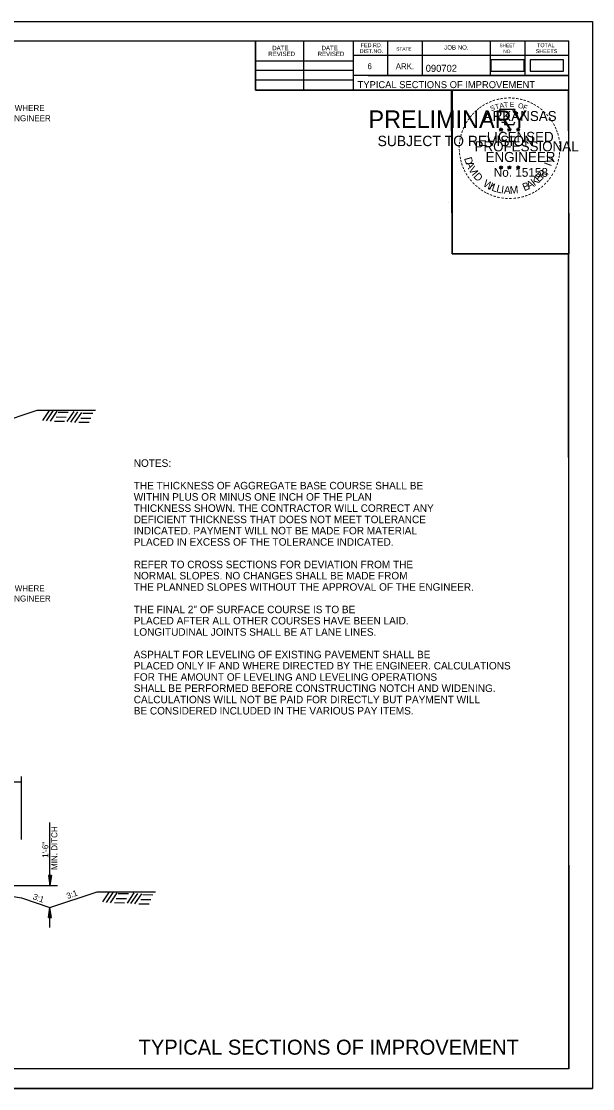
# Model space of a CAD drawing. Extents: x 1371763 to 1372860, y 385599 to 385872.
# Drawn here: x 1372402.6 to 1372459.7, y 385598.6 to 385705.3 of the extents above; entities that cross this region are included whole.
import ezdxf

# ---------------------------------------------------------------- set-up
doc = ezdxf.new("R2010")
doc.units = 0
for name, color, linetype in [('R_Border', 7, 'Continuous'), ('R_Border PE', 7, 'Continuous'), ('R_Border Prem', 7, 'Continuous'), ('R_Dimension', 7, 'Continuous'), ('R_Draft', 7, 'Continuous'), ('R_Fin Surface', 7, 'Continuous'), ('R_No Plot', 7, 'Continuous')]:
    doc.layers.add(name, color=color, linetype=linetype)

msp = doc.modelspace()

# ---------------------------------------------------------------- linework, layer by layer
at = {"layer": 'R_Border'}
for p, q in [((1372299.21, 385703.31), (1372457.3, 385703.31)), ((1372425.98, 385698.37), (1372425.98, 385703.31)), ((1372430.82, 385698.37), (1372430.82, 385703.31)), ((1372435.75, 385703.31), (1372435.75, 385698.37)), ((1372439.17, 385703.31), (1372439.17, 385699.84)), ((1372442.64, 385703.31), (1372442.64, 385699.84)), ((1372449.43, 385703.31), (1372449.43, 385699.84)), ((1372452.9, 385703.31), (1372452.9, 385699.84)), ((1372457.3, 385600.58), (1372457.3, 385703.31)), ((1372457.3, 385701.84), (1372435.75, 385701.84)), ((1372457.3, 385701.85), (1372457.3, 385701.85)), ((1372425.98, 385701.3), (1372435.75, 385701.3)), ((1372425.98, 385700.37), (1372435.75, 385700.37)), ((1372457.3, 385699.84), (1372435.75, 385699.84)), ((1372437.23, 385699.84), (1372457.3, 385699.84)), ((1372425.98, 385699.4), (1372435.75, 385699.4)), ((1372457.3, 385698.37), (1372425.98, 385698.37)), ((1372457.3, 385600.58), (1372299.21, 385600.58))]:
    msp.add_line(p, q, dxfattribs=at)
at = {"layer": 'R_Border PE'}
for p, q in [((1372450.34, 385694.49), (1372450.51, 385694.44)), ((1372450.34, 385694.49), (1372450.47, 385694.47)), ((1372450.34, 385694.49), (1372450.46, 385694.43)), ((1372450.41, 385694.29), (1372450.51, 385694.44)), ((1372450.41, 385694.29), (1372450.47, 385694.41)), ((1372450.41, 385694.29), (1372450.51, 385694.4)), ((1372450.51, 385694.62), (1372450.49, 385694.5)), ((1372450.51, 385694.44), (1372450.51, 385694.62)), ((1372450.51, 385694.62), (1372450.54, 385694.5)), ((1372450.69, 385694.49), (1372450.51, 385694.44)), ((1372450.62, 385694.29), (1372450.51, 385694.44)), ((1372450.62, 385694.29), (1372450.51, 385694.4)), ((1372450.69, 385694.49), (1372450.55, 385694.47)), ((1372450.62, 385694.29), (1372450.55, 385694.44)), ((1372450.69, 385694.49), (1372450.59, 385694.44)), ((1372451.18, 385694.49), (1372451.35, 385694.44)), ((1372451.18, 385694.49), (1372451.3, 385694.47)), ((1372451.18, 385694.49), (1372451.29, 385694.43)), ((1372451.24, 385694.29), (1372451.35, 385694.44)), ((1372451.24, 385694.29), (1372451.3, 385694.41)), ((1372451.24, 385694.29), (1372451.35, 385694.4)), ((1372451.35, 385694.62), (1372451.33, 385694.5)), ((1372451.35, 385694.44), (1372451.35, 385694.62)), ((1372451.35, 385694.62), (1372451.37, 385694.5)), ((1372451.52, 385694.49), (1372451.35, 385694.44)), ((1372451.46, 385694.29), (1372451.35, 385694.44)), ((1372451.46, 385694.29), (1372451.35, 385694.4)), ((1372451.52, 385694.49), (1372451.38, 385694.47)), ((1372451.46, 385694.29), (1372451.39, 385694.44)), ((1372451.52, 385694.49), (1372451.42, 385694.44)), ((1372452.06, 385694.49), (1372452.23, 385694.43)), ((1372452.06, 385694.49), (1372452.18, 385694.47)), ((1372452.06, 385694.49), (1372452.18, 385694.43)), ((1372452.12, 385694.28), (1372452.23, 385694.43)), ((1372452.12, 385694.28), (1372452.19, 385694.41)), ((1372452.12, 385694.28), (1372452.23, 385694.39)), ((1372452.23, 385694.62), (1372452.21, 385694.49)), ((1372452.23, 385694.43), (1372452.23, 385694.62)), ((1372452.23, 385694.62), (1372452.26, 385694.49)), ((1372452.41, 385694.49), (1372452.23, 385694.43)), ((1372452.34, 385694.28), (1372452.23, 385694.43)), ((1372452.34, 385694.28), (1372452.23, 385694.39)), ((1372452.41, 385694.49), (1372452.26, 385694.46)), ((1372452.34, 385694.28), (1372452.27, 385694.43)), ((1372452.41, 385694.49), (1372452.3, 385694.44)), ((1372450.34, 385690.71), (1372450.51, 385690.65)), ((1372450.34, 385690.71), (1372450.46, 385690.69)), ((1372450.34, 385690.71), (1372450.46, 385690.65)), ((1372450.4, 385690.5), (1372450.51, 385690.65)), ((1372450.4, 385690.5), (1372450.47, 385690.63)), ((1372450.4, 385690.5), (1372450.51, 385690.61)), ((1372450.51, 385690.83), (1372450.49, 385690.71)), ((1372450.51, 385690.65), (1372450.51, 385690.83)), ((1372450.51, 385690.83), (1372450.54, 385690.71)), ((1372450.69, 385690.71), (1372450.51, 385690.65)), ((1372450.62, 385690.5), (1372450.51, 385690.65)), ((1372450.62, 385690.5), (1372450.51, 385690.61)), ((1372450.69, 385690.71), (1372450.54, 385690.68)), ((1372450.62, 385690.5), (1372450.55, 385690.65)), ((1372450.69, 385690.71), (1372450.58, 385690.66)), ((1372451.17, 385690.71), (1372451.35, 385690.65)), ((1372451.17, 385690.71), (1372451.3, 385690.69)), ((1372451.17, 385690.71), (1372451.29, 385690.65)), ((1372451.24, 385690.5), (1372451.35, 385690.65)), ((1372451.24, 385690.5), (1372451.3, 385690.63)), ((1372451.24, 385690.5), (1372451.35, 385690.61)), ((1372451.35, 385690.83), (1372451.33, 385690.71)), ((1372451.35, 385690.65), (1372451.35, 385690.83)), ((1372451.35, 385690.83), (1372451.37, 385690.71)), ((1372451.52, 385690.71), (1372451.35, 385690.65)), ((1372451.45, 385690.5), (1372451.35, 385690.65)), ((1372451.45, 385690.5), (1372451.35, 385690.61)), ((1372451.52, 385690.71), (1372451.38, 385690.68)), ((1372451.45, 385690.5), (1372451.39, 385690.65)), ((1372451.52, 385690.71), (1372451.42, 385690.66)), ((1372452.06, 385690.7), (1372452.23, 385690.65)), ((1372452.06, 385690.7), (1372452.18, 385690.68)), ((1372452.06, 385690.7), (1372452.17, 385690.64)), ((1372452.12, 385690.5), (1372452.23, 385690.65)), ((1372452.12, 385690.5), (1372452.19, 385690.62)), ((1372452.12, 385690.5), (1372452.23, 385690.61)), ((1372452.23, 385690.83), (1372452.21, 385690.7)), ((1372452.23, 385690.65), (1372452.23, 385690.83)), ((1372452.23, 385690.83), (1372452.26, 385690.7)), ((1372452.4, 385690.7), (1372452.23, 385690.65)), ((1372452.34, 385690.5), (1372452.23, 385690.65)), ((1372452.34, 385690.5), (1372452.23, 385690.61)), ((1372452.4, 385690.7), (1372452.26, 385690.68)), ((1372452.34, 385690.5), (1372452.27, 385690.64)), ((1372452.4, 385690.7), (1372452.3, 385690.65))]:
    msp.add_line(p, q, dxfattribs=at)
for points in [[(1372450.36, 385696.43), (1372450.5, 385696.02)], [(1372452.12, 385695.97), (1372452.19, 385696.11), (1372451.84, 385696.1), (1372451.92, 385696.43), (1372450.36, 385696.43)], [(1372450.61, 385695.22), (1372450.61, 385695.18), (1372450.89, 385695.17), (1372450.86, 385694.93), (1372451.8, 385694.93), (1372451.9, 385695.2)], [(1372450.51, 385694.62), (1372450.62, 385694.29), (1372450.34, 385694.49), (1372450.69, 385694.49), (1372450.41, 385694.29), (1372450.51, 385694.62)], [(1372451.35, 385694.62), (1372451.46, 385694.29), (1372451.18, 385694.49), (1372451.52, 385694.49), (1372451.24, 385694.29), (1372451.35, 385694.62)], [(1372452.23, 385694.62), (1372452.34, 385694.28), (1372452.06, 385694.49), (1372452.41, 385694.49), (1372452.12, 385694.28), (1372452.23, 385694.62)], [(1372450.51, 385690.83), (1372450.62, 385690.5), (1372450.34, 385690.71), (1372450.69, 385690.71), (1372450.4, 385690.5), (1372450.51, 385690.83)], [(1372451.35, 385690.83), (1372451.45, 385690.5), (1372451.17, 385690.71), (1372451.52, 385690.71), (1372451.24, 385690.5), (1372451.35, 385690.83)], [(1372452.23, 385690.83), (1372452.34, 385690.5), (1372452.06, 385690.7), (1372452.4, 385690.7), (1372452.12, 385690.5), (1372452.23, 385690.83)]]:
    msp.add_lwpolyline(points, dxfattribs=at)
for centre, radius in [((1372450.51, 385694.44), 0.0861), ((1372450.51, 385694.44), 0.0723), ((1372450.51, 385694.44), 0.0579), ((1372450.51, 385694.44), 0.0495), ((1372450.51, 385694.44), 0.0374), ((1372450.51, 385694.44), 0.0248), ((1372450.51, 385694.44), 0.0148), ((1372451.35, 385694.44), 0.0861), ((1372451.35, 385694.44), 0.0723), ((1372451.35, 385694.44), 0.0579), ((1372451.35, 385694.44), 0.0495), ((1372451.35, 385694.44), 0.0374), ((1372451.35, 385694.44), 0.0248), ((1372451.35, 385694.44), 0.0148), ((1372452.23, 385694.43), 0.0861), ((1372452.23, 385694.43), 0.0723), ((1372452.23, 385694.43), 0.0579), ((1372452.23, 385694.43), 0.0495), ((1372452.23, 385694.43), 0.0374), ((1372452.23, 385694.43), 0.0248), ((1372452.23, 385694.43), 0.0148), ((1372450.51, 385690.65), 0.0861), ((1372450.51, 385690.65), 0.0723), ((1372450.51, 385690.65), 0.0579), ((1372450.51, 385690.65), 0.0495), ((1372450.51, 385690.65), 0.0374), ((1372450.51, 385690.65), 0.0248), ((1372450.51, 385690.65), 0.0148), ((1372451.35, 385690.65), 0.0861), ((1372451.35, 385690.65), 0.0723), ((1372451.35, 385690.65), 0.0579), ((1372451.35, 385690.65), 0.0495), ((1372451.35, 385690.65), 0.0374), ((1372451.35, 385690.65), 0.0248), ((1372451.35, 385690.65), 0.0148), ((1372452.23, 385690.65), 0.0861), ((1372452.23, 385690.65), 0.0723), ((1372452.23, 385690.65), 0.0579), ((1372452.23, 385690.65), 0.0495), ((1372452.23, 385690.65), 0.0374), ((1372452.23, 385690.65), 0.0248), ((1372452.23, 385690.65), 0.0148)]:
    msp.add_circle(centre, radius, dxfattribs=at)
at = {"layer": 'R_Draft'}
for p, q in [((1372404.72, 385665.36), (1372405.4, 385666.37)), ((1372405.08, 385665.32), (1372405.75, 385666.32)), ((1372405.48, 385665.28), (1372406.15, 385666.28)), ((1372406.05, 385665.72), (1372407.07, 385665.71)), ((1372406.25, 385666.21), (1372407.27, 385666.2)), ((1372407.17, 385665.26), (1372407.85, 385666.26)), ((1372407.53, 385665.21), (1372408.21, 385666.22)), ((1372407.93, 385665.17), (1372408.61, 385666.17)), ((1372408.51, 385665.61), (1372409.53, 385665.61)), ((1372408.71, 385666.1), (1372409.73, 385666.09)), ((1372405.88, 385665.3), (1372406.9, 385665.29)), ((1372408.33, 385665.19), (1372409.35, 385665.18)), ((1372378.58, 385629.25), (1372402.58, 385629.25)), ((1372402.58, 385623.49), (1372402.58, 385629.79)), ((1372405.43, 385618.88), (1372405.43, 385625.18)), ((1372386.58, 385620.31), (1372402.58, 385617.64)), ((1372405.28, 385619.88), (1372405.43, 385618.88)), ((1372405.58, 385619.88), (1372405.28, 385619.88)), ((1372405.3, 385619.88), (1372405.43, 385619.05)), ((1372405.33, 385619.88), (1372405.43, 385619.22)), ((1372405.35, 385619.88), (1372405.43, 385619.39)), ((1372405.38, 385619.88), (1372405.43, 385619.56)), ((1372405.4, 385619.88), (1372405.43, 385619.72)), ((1372405.58, 385619.88), (1372405.43, 385618.88)), ((1372405.47, 385619.88), (1372405.43, 385619.56)), ((1372405.52, 385619.88), (1372405.43, 385619.22)), ((1372405.55, 385619.88), (1372405.43, 385619.05)), ((1372405.5, 385619.88), (1372405.43, 385619.39)), ((1372405.45, 385619.88), (1372405.43, 385619.72)), ((1372397.32, 385618.88), (1372406.18, 385618.88)), ((1372410.72, 385617.24), (1372411.4, 385618.25)), ((1372411.08, 385617.2), (1372411.76, 385618.2)), ((1372411.48, 385617.16), (1372412.16, 385618.16)), ((1372412.06, 385617.6), (1372413.07, 385617.59)), ((1372412.26, 385618.09), (1372413.28, 385618.08)), ((1372413.17, 385617.13), (1372413.85, 385618.14)), ((1372413.53, 385617.09), (1372414.21, 385618.09)), ((1372413.93, 385617.05), (1372414.61, 385618.05)), ((1372414.51, 385617.49), (1372415.53, 385617.49)), ((1372414.71, 385617.98), (1372415.73, 385617.97)), ((1372405.28, 385615.69), (1372405.43, 385616.69)), ((1372405.3, 385615.69), (1372405.43, 385616.53)), ((1372405.33, 385615.69), (1372405.43, 385616.35)), ((1372405.58, 385615.69), (1372405.43, 385616.69)), ((1372405.43, 385614.69), (1372405.43, 385616.69)), ((1372405.55, 385615.69), (1372405.43, 385616.53)), ((1372405.52, 385615.69), (1372405.43, 385616.35)), ((1372411.88, 385617.18), (1372412.9, 385617.17)), ((1372414.33, 385617.07), (1372415.35, 385617.06)), ((1372405.28, 385615.69), (1372405.58, 385615.69)), ((1372405.35, 385615.69), (1372405.43, 385616.19)), ((1372405.38, 385615.69), (1372405.43, 385616.02)), ((1372405.4, 385615.69), (1372405.43, 385615.85)), ((1372405.5, 385615.69), (1372405.43, 385616.19)), ((1372405.47, 385615.69), (1372405.43, 385616.02)), ((1372405.45, 385615.69), (1372405.43, 385615.85))]:
    msp.add_line(p, q, dxfattribs=at)
for points in [[(1372449.49, 385700.26), (1372452.83, 385700.26), (1372452.83, 385701.41), (1372449.49, 385701.41)], [(1372453.43, 385700.26), (1372456.77, 385700.26), (1372456.77, 385701.41), (1372453.43, 385701.41)]]:
    msp.add_lwpolyline(points, close=True, dxfattribs=at)
at = {"layer": 'R_Fin Surface'}
for p, q in [((1372399.42, 385664.81), (1372404.17, 385666.4)), ((1372404.17, 385666.4), (1372409.98, 385666.4)), ((1372402.58, 385617.64), (1372405.43, 385616.69)), ((1372405.43, 385616.69), (1372410.17, 385618.27)), ((1372410.17, 385618.27), (1372415.99, 385618.27))]:
    msp.add_line(p, q, dxfattribs=at)
at = {"layer": 'R_No Plot'}
for p, q in [((1372293.01, 385705.25), (1372459.67, 385705.25)), ((1372445.31, 385687.14), (1372445.31, 385687.14)), ((1372293.01, 385598.59), (1372459.67, 385598.59))]:
    msp.add_line(p, q, dxfattribs=at)
for points in [[(1372293, 385705.25), (1372459.67, 385705.25), (1372459.67, 385598.59), (1372293, 385598.59)], [(1372416.17, 385703.31), (1372425.98, 385703.31), (1372425.98, 385698.37), (1372434.03, 385698.37), (1372445.63, 385698.37), (1372445.63, 385682.03), (1372457.24, 385682.03), (1372457.3, 385600.58), (1372299.21, 385600.58), (1372299.21, 385703.31)], [(1372445.56, 385698.37), (1372457.24, 385698.37), (1372457.31, 385682.03), (1372445.63, 385682.03)]]:
    msp.add_lwpolyline(points, close=True, dxfattribs=at)

# ---------------------------------------------------------------- texts
at = {"layer": 'R_Border'}
for s, height, p in [('DATE', 0.44, (1372427.65, 385702.37)), ('DATE', 0.44, (1372432.58, 385702.37)), ('FED.RD.', 0.391, (1372436.49, 385702.67)), ('STATE', 0.342, (1372440.05, 385702.33)), ('JOB NO.', 0.44, (1372444.84, 385702.43)), ('SHEET', 0.342, (1372450.36, 385702.67)), ('TOTAL', 0.391, (1372454.12, 385702.67)), ('REVISED', 0.44, (1372427.26, 385701.78)), ('REVISED', 0.44, (1372432.19, 385701.78)), ('DIST.NO.', 0.391, (1372436.39, 385702.08)), ('NO.', 0.342, (1372450.75, 385702.08)), ('SHEETS', 0.391, (1372453.98, 385702.08)), ('6', 0.586, (1372437.17, 385700.47)), ('ARK.', 0.586, (1372440, 385700.47)), ('090702', 0.7, (1372442.99, 385700.21)), ('TYPICAL SECTIONS OF IMPROVEMENT', 0.7, (1372436.18, 385698.58))]:
    msp.add_text(s, height=height, dxfattribs=at).set_placement(p)
at = {"layer": 'R_Border PE'}
for s, height, rotation, p in [('-', 0.8, 19.1761, (1372449.73, 385697)), ('-', 0.8, 13.6302, (1372450.11, 385697.12)), ('-', 0.8, 10.2193, (1372450.45, 385697.2)), ('-', 0.8, 5.8968, (1372450.81, 385697.25)), ('-', 0.8, 0.1862, (1372451.2, 385697.29)), ('-', 0.8, 357.743, (1372451.56, 385697.28)), ('-', 0.8, 352.1617, (1372451.93, 385697.25)), ('-', 0.8, 347.2049, (1372452.29, 385697.2)), ('-', 0.8, 342.3362, (1372452.61, 385697.12)), ('-', 0.8, 337.8551, (1372452.98, 385697.01)), ('-', 0.8, 42.9622, (1372448.06, 385695.92)), ('-', 0.8, 38.9507, (1372448.28, 385696.13)), ('-', 0.8, 36.2317, (1372448.51, 385696.32)), ('-', 0.8, 34.0636, (1372448.8, 385696.52)), ('-', 0.8, 28.7918, (1372449.1, 385696.7)), ('-', 0.8, 24.3072, (1372449.42, 385696.86)), ('S', 0.5, 21.594, (1372449.54, 385696.27)), ('T', 0.5, 16.4036, (1372450, 385696.44)), ('A', 0.5, 11.2132, (1372450.41, 385696.56)), ('T', 0.5, 6.0228, (1372450.83, 385696.65)), ('E', 0.5, 0.8323, (1372451.39, 385696.7)), ('O', 0.5, 350.4515, (1372452.19, 385696.6)), ('F', 0.5, 340.0707, (1372452.66, 385696.48)), ('-', 0.8, 334.1211, (1372453.29, 385696.87)), ('-', 0.8, 329.6409, (1372453.58, 385696.73)), ('-', 0.8, 325.8627, (1372453.9, 385696.55)), ('-', 0.8, 320.5297, (1372454.21, 385696.34)), ('-', 0.8, 315.5786, (1372454.51, 385696.09)), ('-', 0.8, 58.0706, (1372447.26, 385694.89)), ('-', 0.8, 54.2325, (1372447.43, 385695.16)), ('-', 0.8, 50.6142, (1372447.63, 385695.44)), ('-', 0.8, 48.4231, (1372447.84, 385695.68)), ('-', 0.8, 309.8797, (1372454.79, 385695.82)), ('-', 0.8, 306.6522, (1372455.06, 385695.52)), ('-', 0.7, 303.6753, (1372455.3, 385695.23)), ('-', 0.8, 72.3945, (1372446.87, 385693.97)), ('-', 0.8, 67.7743, (1372446.98, 385694.28)), ('-', 0.8, 62.8713, (1372447.11, 385694.59)), ('-', 0.8, 299.6684, (1372455.46, 385694.93)), ('-', 0.8, 294.6628, (1372455.62, 385694.62)), ('-', 0.8, 290.5728, (1372455.75, 385694.34)), ('-', 0.8, 85.1863, (1372446.67, 385692.91)), ('-', 0.8, 81.2013, (1372446.7, 385693.25)), ('-', 0.8, 75.461, (1372446.77, 385693.61)), ('-', 0.8, 285.1233, (1372455.87, 385694.05)), ('-', 0.8, 280.5493, (1372455.97, 385693.68)), ('-', 0.8, 276.5962, (1372456.05, 385693.29)), ('-', 0.8, 89.0622, (1372446.65, 385692.56)), ('-', 0.8, 94.1959, (1372446.67, 385692.2)), ('-', 0.8, 98.9479, (1372446.71, 385691.86)), ('-', 0.8, 263.5172, (1372456.08, 385692.28)), ('-', 0.8, 274.3301, (1372456.08, 385692.93)), ('-', 0.8, 269.9407, (1372456.09, 385692.61)), ('-', 0.8, 101.7149, (1372446.78, 385691.5)), ('-', 0.8, 105.4578, (1372446.86, 385691.2)), ('-', 0.8, 109.0874, (1372446.96, 385690.88)), ('D', 0.77, 286.2848, (1372446.82, 385691.56)), ('A', 0.77, 292.7835, (1372446.97, 385691.06)), ('I', 0.77, 69.0301, (1372455.5, 385690.71)), ('V', 0.77, 72.6573, (1372455.62, 385690.98)), ('-', 0.8, 252.8681, (1372455.9, 385691.26)), ('-', 0.8, 255.7626, (1372455.99, 385691.62)), ('-', 0.8, 260.9953, (1372456.05, 385691.95)), ('-', 0.8, 114.0643, (1372447.09, 385690.58)), ('-', 0.8, 115.7289, (1372447.24, 385690.28)), ('-', 0.8, 120.4471, (1372447.42, 385689.98)), ('V', 0.77, 300.7936, (1372447.22, 385690.47)), ('I', 0.77, 308.3502, (1372447.54, 385689.96)), ('D', 0.77, 311.9774, (1372447.71, 385689.72)), ('E', 0.77, 44.0175, (1372454.31, 385689.12)), ('R', 0.77, 50.3651, (1372454.68, 385689.47)), (',', 0.77, 57.4684, (1372455.04, 385689.91)), ('-', 0.8, 239.0712, (1372455.46, 385690.23)), ('-', 0.8, 244.6197, (1372455.66, 385690.6)), ('-', 0.8, 247.8887, (1372455.79, 385690.92)), ('-', 0.8, 125.8934, (1372447.62, 385689.7)), ('-', 0.8, 130.7181, (1372447.85, 385689.43)), ('-', 0.8, 134.2238, (1372448.11, 385689.15)), ('-', 0.8, 138.9338, (1372448.38, 385688.92)), ('W', 0.77, 328.0731, (1372448.65, 385688.84)), ('I', 0.77, 336.6877, (1372449.25, 385688.48)), ('L', 0.77, 340.3149, (1372449.51, 385688.36)), ('L', 0.77, 346.6625, (1372449.99, 385688.19)), ('I', 0.77, 353.0101, (1372450.49, 385688.07)), ('A', 0.77, 356.6373, (1372450.78, 385688.03)), ('M', 0.77, 4.6473, (1372451.42, 385688)), ('B', 0.77, 22.8589, (1372452.85, 385688.27)), ('A', 0.77, 28.9042, (1372453.3, 385688.45)), ('K', 0.77, 36.9143, (1372453.86, 385688.77)), ('-', 0.8, 221.0851, (1372454.55, 385689.08)), ('-', 0.8, 225.7653, (1372454.81, 385689.34)), ('-', 0.8, 231.2538, (1372455.05, 385689.62)), ('-', 0.8, 233.8452, (1372455.26, 385689.9)), ('-', 0.8, 144.6463, (1372448.65, 385688.72)), ('-', 0.8, 148.0898, (1372448.93, 385688.53)), ('-', 0.8, 151.5704, (1372449.22, 385688.37)), ('-', 0.8, 154.6002, (1372449.48, 385688.25)), ('-', 0.8, 158.5612, (1372449.8, 385688.12)), ('-', 0.8, 162.7983, (1372450.14, 385688.01)), ('-', 0.8, 167.5555, (1372450.5, 385687.93)), ('-', 0.8, 195.4743, (1372452.77, 385688.06)), ('-', 0.8, 199.4643, (1372453.1, 385688.18)), ('-', 0.8, 204.2516, (1372453.41, 385688.32)), ('-', 0.8, 207.3568, (1372453.73, 385688.48)), ('-', 0.8, 212.2491, (1372454.01, 385688.65)), ('-', 0.8, 215.7363, (1372454.27, 385688.85)), ('-', 0.8, 173.1155, (1372450.88, 385687.88)), ('-', 0.8, 176.5183, (1372451.26, 385687.85)), ('-', 0.8, 181.5918, (1372451.63, 385687.86)), ('-', 0.8, 185.8167, (1372452.03, 385687.9)), ('-', 0.8, 191.2858, (1372452.4, 385687.96))]:
    msp.add_text(s, height=height, rotation=rotation, dxfattribs=at).set_placement(p)
for s, height, p in [('ARKANSAS', 1, (1372448.79, 385695.29)), ('LICENSED', 1, (1372449.09, 385693.21)), ('PROFESSIONAL', 1, (1372447.87, 385692.26)), ('ENGINEER', 1, (1372448.97, 385691.2)), ('No. 15158', 0.878, (1372449.79, 385689.72)), ('AAMU', 0.00001, (1372451.31, 385688))]:
    msp.add_text(s, height=height, dxfattribs=at).set_placement(p)
at = {"layer": 'R_Border Prem'}
for s, height, p in [('PRELIMINARY', 1.75, (1372437.27, 385694.6)), ('DWB', 0.005, (1372437.65, 385695.52)), ('SUBJECT TO REVISION', 1.0376, (1372438.18, 385692.78))]:
    msp.add_text(s, height=height, dxfattribs=at).set_placement(p)
at = {"layer": 'R_Dimension'}
msp.add_text('TYPICAL SECTIONS OF IMPROVEMENT', height=1.5, dxfattribs=at).set_placement((1372414.3, 385601.98))
at = {"layer": 'R_Draft'}
for s, rotation, p in [('*TO BE USED IF AND WHERE ', 360, (1372393.67, 385696.29)), ('DIRECTED BY THE ENGINEER', 360, (1372393.88, 385695.27)), ('*TO BE USED IF AND WHERE ', 360, (1372393.67, 385648.29)), ('DIRECTED BY THE ENGINEER', 360, (1372393.88, 385647.27)), ('MIN. DITCH', 90, (1372406.17, 385620.44)), ('1\'-6"', 90, (1372405.27, 385621.65)), ('3:1', 19.9978, (1372407.21, 385617.53)), ('3:1', 340.0022, (1372403.67, 385617.54))]:
    msp.add_text(s, height=0.6, rotation=rotation, dxfattribs=at).set_placement(p)
for s, p in [('NOTES:', (1372413.81, 385660.73)), ('THE THICKNESS OF AGGREGATE BASE COURSE SHALL BE', (1372413.81, 385658.48)), ('WITHIN PLUS OR MINUS ONE INCH OF THE PLAN', (1372413.81, 385657.35)), ('THICKNESS SHOWN. THE CONTRACTOR WILL CORRECT ANY', (1372413.81, 385656.23)), ('DEFICIENT THICKNESS THAT DOES NOT MEET TOLERANCE ', (1372413.81, 385655.1)), ('INDICATED. PAYMENT WILL NOT BE MADE FOR MATERIAL', (1372413.81, 385653.98)), ('PLACED IN EXCESS OF THE TOLERANCE INDICATED.', (1372413.81, 385652.85)), ('REFER TO CROSS SECTIONS FOR DEVIATION FROM THE', (1372413.81, 385650.6)), ('NORMAL SLOPES. NO CHANGES SHALL BE MADE FROM', (1372413.81, 385649.48)), ('THE PLANNED SLOPES WITHOUT THE APPROVAL OF THE ENGINEER.', (1372413.81, 385648.35)), ('THE FINAL 2" OF SURFACE COURSE IS TO BE', (1372413.81, 385646.1)), ('PLACED AFTER ALL OTHER COURSES HAVE BEEN LAID.', (1372413.81, 385644.98)), ('LONGITUDINAL JOINTS SHALL BE AT LANE LINES.', (1372413.81, 385643.85)), ('ASPHALT FOR LEVELING OF EXISTING PAVEMENT SHALL BE', (1372413.81, 385641.6)), ('PLACED ONLY IF AND WHERE DIRECTED BY THE ENGINEER. CALCULATIONS', (1372413.81, 385640.48)), ('FOR THE AMOUNT OF LEVELING AND LEVELING OPERATIONS', (1372413.81, 385639.35)), ('SHALL BE PERFORMED BEFORE CONSTRUCTING NOTCH AND WIDENING.', (1372413.81, 385638.23)), ('CALCULATIONS WILL NOT BE PAID FOR DIRECTLY BUT PAYMENT WILL', (1372413.81, 385637.1)), ('BE CONSIDERED INCLUDED IN THE VARIOUS PAY ITEMS.', (1372413.81, 385635.98))]:
    msp.add_text(s, height=0.75, dxfattribs=at).set_placement(p)

doc.saveas('drawing.dxf')
